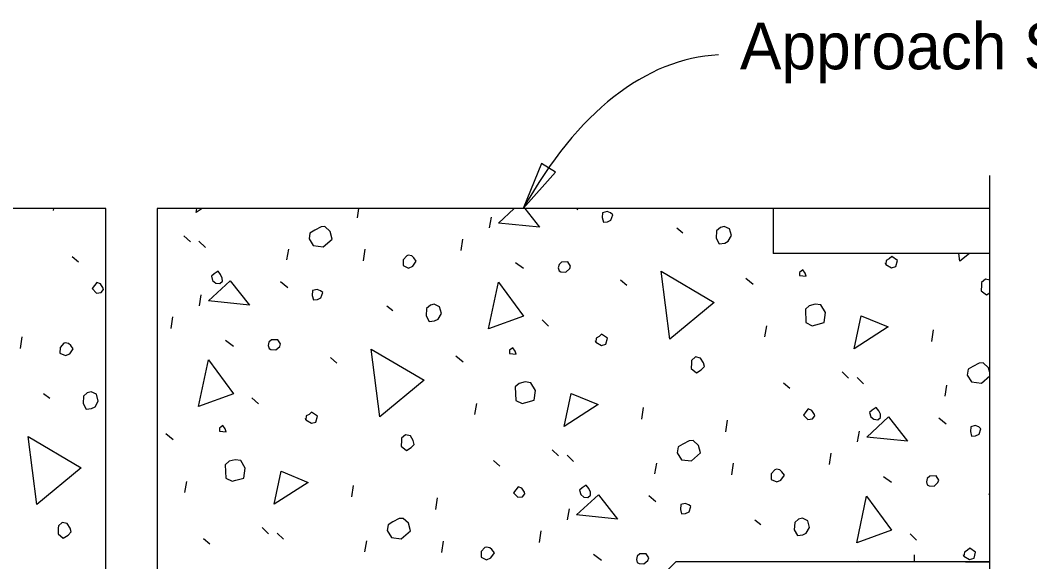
# Model space of a CAD drawing. Extents: x 112544 to 112597.1, y 111084 to 111107.1.
# Drawn here: x 112569.508 to 112572.786, y 111103.433 to 111105.19 of the extents above; entities that cross this region are included whole.
import ezdxf

# ---------------------------------------------------------------- set-up
doc = ezdxf.new("R2010")
doc.units = 0
for name, color, linetype in [('Dimension', 7, 'Continuous'), ('Miscellaneous', 7, 'Continuous'), ('SupstrConc', 7, 'Continuous'), ('TextStructures', 7, 'Continuous')]:
    doc.layers.add(name, color=color, linetype=linetype)

msp = doc.modelspace()

# ---------------------------------------------------------------- linework, layer by layer
at = {"layer": 'Dimension'}
msp.add_lwpolyline([(112571.1413, 111104.5785), (112571.2459, 111104.6974), (112571.2009, 111104.7252)], close=True, dxfattribs=at)
msp.add_lwpolyline([(112572.656, 111101.6604), (112572.656, 111101.9268), (112572.7335, 111101.9268), (112572.656, 111101.9606), (112572.5785, 111101.9943), (112572.656, 111101.9943), (112572.656, 111104.6864)], dxfattribs=at)
msp.add_ellipse((112571.8864, 111102.7097), major_axis=(0.1111, -2.3674), ratio=0.464296, start_param=3.141604, end_param=3.781059, dxfattribs=at)
at = {"layer": 'Miscellaneous'}
for p, q in [((112569.6165, 111104.5729), (112569.6175, 111104.5786)), ((112570.6036, 111104.5487), (112570.6079, 111104.5786)), ((112571.3142, 111104.5786), (112571.3188, 111104.5747)), ((112572.656, 111104.5786), (112571.9525, 111104.5786)), ((112571.0317, 111104.5159), (112571.0378, 111104.5512)), ((112571.64, 111104.5158), (112571.6596, 111104.5004)), ((112570.0394, 111104.4907), (112570.0604, 111104.4704)), ((112570.0882, 111104.4727), (112570.1092, 111104.4525)), ((112570.9402, 111104.4422), (112570.9456, 111104.4799)), ((112570.3737, 111104.412), (112570.3798, 111104.4473)), ((112570.623, 111104.409), (112570.6284, 111104.4467)), ((112569.6772, 111104.4235), (112569.6976, 111104.4056)), ((112571.1161, 111104.4039), (112571.1419, 111104.3849)), ((112570.3536, 111104.342), (112570.377, 111104.3223)), ((112571.4572, 111104.3478), (112571.4775, 111104.3299)), ((112571.8646, 111104.3534), (112571.888, 111104.3338)), ((112570.0899, 111104.2635), (112570.096, 111104.2988)), ((112570.6982, 111104.2635), (112570.7179, 111104.248)), ((112569.9984, 111104.1898), (112570.0038, 111104.2275)), ((112571.2023, 111104.2174), (112571.2233, 111104.1971)), ((112571.9261, 111104.1628), (112571.9321, 111104.1981)), ((112572.4685, 111104.1477), (112572.4739, 111104.1854)), ((112569.5088, 111104.1247), (112569.5143, 111104.1624)), ((112570.1743, 111104.1516), (112570.2001, 111104.1326)), ((112570.5154, 111104.0955), (112570.5358, 111104.0776)), ((112570.9229, 111104.1011), (112570.9462, 111104.0815)), ((112572.1766, 111104.0488), (112572.1976, 111104.0285)), ((112571.9868, 111104.0135), (112572.0071, 111103.9956)), ((112572.2254, 111104.0308), (112572.2464, 111104.0106)), ((112569.5841, 111103.9792), (112569.6037, 111103.9638)), ((112572.5109, 111103.9701), (112572.517, 111104.0054)), ((112570.2605, 111103.965), (112570.2815, 111103.9448)), ((112570.9843, 111103.9105), (112570.9904, 111103.9458)), ((112571.5267, 111103.8954), (112571.5321, 111103.9331)), ((112571.7991, 111103.8545), (112571.8045, 111103.8922)), ((112572.4908, 111103.9001), (112572.5142, 111103.8804)), ((112569.9811, 111103.8487), (112570.0045, 111103.8291)), ((112572.2271, 111103.8216), (112572.2332, 111103.8569)), ((112571.2348, 111103.7965), (112571.2558, 111103.7762)), ((112571.2837, 111103.7785), (112571.3046, 111103.7582)), ((112572.1356, 111103.7479), (112572.141, 111103.7856)), ((112571.045, 111103.7611), (112571.0653, 111103.7433)), ((112571.5691, 111103.7178), (112571.5752, 111103.7531)), ((112571.8184, 111103.7147), (112571.8238, 111103.7524)), ((112570.0425, 111103.6581), (112570.0486, 111103.6934)), ((112570.5849, 111103.643), (112570.5903, 111103.6807)), ((112572.3115, 111103.7097), (112572.3373, 111103.6907)), ((112571.5491, 111103.6477), (112571.5724, 111103.6281)), ((112572.6526, 111103.6535), (112572.656, 111103.6506)), ((112570.8573, 111103.6021), (112570.8627, 111103.6398)), ((112571.2854, 111103.5693), (112571.2914, 111103.6046)), ((112571.8936, 111103.5692), (112571.9133, 111103.5538)), ((112570.2931, 111103.5441), (112570.314, 111103.5238)), ((112570.3419, 111103.5261), (112570.3628, 111103.5059)), ((112571.1938, 111103.4956), (112571.1993, 111103.5333)), ((112572.3977, 111103.5231), (112572.4187, 111103.5028)), ((112570.1032, 111103.5088), (112570.1236, 111103.4909)), ((112570.6273, 111103.4654), (112570.6334, 111103.5007)), ((112570.8766, 111103.4624), (112570.882, 111103.5)), ((112571.3697, 111103.4573), (112571.3955, 111103.4383)), ((112572.5774, 111103.4328), (112572.656, 111103.4328))]:
    msp.add_line(p, q, dxfattribs=at)
for points in [[(112570.0788, 111104.566), (112570.0815, 111104.5786)], [(112570.0984, 111104.5786), (112570.0788, 111104.566)], [(112571.0612, 111104.5316), (112571.1118, 111104.5786)], [(112571.1462, 111104.5786), (112571.1942, 111104.518), (112571.0612, 111104.5316)], [(112571.398, 111104.5493), (112571.4019, 111104.5349), (112571.4146, 111104.5357), (112571.4261, 111104.5413), (112571.4319, 111104.5584), (112571.4251, 111104.5644), (112571.4135, 111104.569), (112571.399, 111104.5651), (112571.398, 111104.5493)], [(112570.4459, 111104.4806), (112570.4596, 111104.4584), (112570.4918, 111104.4541), (112570.5211, 111104.48), (112570.5146, 111104.5042), (112570.4974, 111104.5203), (112570.4847, 111104.5194), (112570.4642, 111104.5088), (112570.4486, 111104.4994), (112570.4459, 111104.4806)], [(112571.7693, 111104.5065), (112571.7679, 111104.4828), (112571.7779, 111104.4648), (112571.7954, 111104.4669), (112571.8069, 111104.4725), (112571.8175, 111104.4909), (112571.8116, 111104.5126), (112571.7939, 111104.5208), (112571.7818, 111104.5176), (112571.7693, 111104.5065)], [(112570.7515, 111104.4123), (112570.7512, 111104.3941), (112570.7689, 111104.3859), (112570.7827, 111104.3922), (112570.794, 111104.4082), (112570.7859, 111104.419), (112570.7792, 111104.4249), (112570.7682, 111104.4272), (112570.7634, 111104.4259), (112570.7515, 111104.4123)], [(112571.2578, 111104.3772), (112571.2639, 111104.3737), (112571.2797, 111104.3727), (112571.2923, 111104.3838), (112571.2952, 111104.3924), (112571.2865, 111104.4056), (112571.2658, 111104.4052), (112571.2575, 111104.3978), (112571.2552, 111104.3869), (112571.2578, 111104.3772)], [(112572.3187, 111104.3975), (112572.3371, 111104.3869), (112572.3516, 111104.3907), (112572.3567, 111104.4102), (112572.3377, 111104.4233), (112572.3293, 111104.4158), (112572.3203, 111104.4108), (112572.3187, 111104.3975), (112572.3174, 111104.4023)], [(112572.5593, 111104.4076), (112572.5561, 111104.4328)], [(112572.5899, 111104.4328), (112572.5593, 111104.4076)], [(112570.1328, 111104.3449), (112570.1427, 111104.3372), (112570.156, 111104.3356), (112570.1644, 111104.343), (112570.1642, 111104.3533), (112570.1586, 111104.3648), (112570.1505, 111104.3755), (112570.1373, 111104.3668), (112570.129, 111104.3594), (112570.1328, 111104.3449)], [(112571.6175, 111104.1552), (112571.5896, 111104.3755), (112571.7617, 111104.2741), (112571.6175, 111104.1552)], [(112572.0386, 111104.3612), (112572.0598, 111104.3591), (112572.0572, 111104.3688), (112572.0492, 111104.3796), (112572.0384, 111104.3715), (112572.0386, 111104.3612)], [(112569.7415, 111104.3191), (112569.7557, 111104.3047), (112569.7708, 111104.3062), (112569.7785, 111104.316), (112569.7772, 111104.3209), (112569.7685, 111104.3341), (112569.7569, 111104.3387), (112569.7492, 111104.3289), (112569.7415, 111104.3191)], [(112570.1194, 111104.2792), (112570.1899, 111104.3447), (112570.2524, 111104.2657), (112570.1194, 111104.2792)], [(112571.0287, 111104.189), (112571.0608, 111104.3399), (112571.1421, 111104.2297), (112571.0287, 111104.189)], [(112572.656, 111104.3467), (112572.6422, 111104.3495), (112572.6296, 111104.3384), (112572.6291, 111104.3305)], [(112570.4563, 111104.297), (112570.4601, 111104.2825), (112570.4729, 111104.2833), (112570.4843, 111104.289), (112570.4901, 111104.3061), (112570.4833, 111104.312), (112570.4717, 111104.3167), (112570.4572, 111104.3128), (112570.4563, 111104.297)], [(112572.6291, 111104.3305), (112572.6288, 111104.3123), (112572.6454, 111104.2987), (112572.656, 111104.305)], [(112570.8275, 111104.2541), (112570.8261, 111104.2305), (112570.8361, 111104.2124), (112570.8537, 111104.2145), (112570.8651, 111104.2202), (112570.8757, 111104.2386), (112570.8699, 111104.2603), (112570.8521, 111104.2685), (112570.8401, 111104.2653), (112570.8275, 111104.2541)], [(112572.0574, 111104.2524), (112572.0587, 111104.2087), (112572.0795, 111104.1988), (112572.0916, 111104.202), (112572.1181, 111104.2091), (112572.1224, 111104.2413), (112572.1081, 111104.266), (112572.0892, 111104.2687), (112572.0699, 111104.2635), (112572.0574, 111104.2524)], [(112572.216, 111104.1241), (112572.2391, 111104.2312), (112572.3264, 111104.195), (112572.216, 111104.1241)], [(112569.6373, 111104.1281), (112569.637, 111104.1099), (112569.6548, 111104.1017), (112569.6686, 111104.108), (112569.6799, 111104.124), (112569.6718, 111104.1347), (112569.665, 111104.1407), (112569.6541, 111104.1429), (112569.6492, 111104.1416), (112569.6373, 111104.1281)], [(112570.316, 111104.1248), (112570.3222, 111104.1213), (112570.338, 111104.1204), (112570.3505, 111104.1315), (112570.3534, 111104.14), (112570.3447, 111104.1532), (112570.3241, 111104.1529), (112570.3157, 111104.1455), (112570.3135, 111104.1345), (112570.316, 111104.1248)], [(112571.3769, 111104.1451), (112571.3953, 111104.1345), (112571.4098, 111104.1384), (112571.4149, 111104.1579), (112571.3959, 111104.1709), (112571.3876, 111104.1635), (112571.3785, 111104.1585), (112571.3769, 111104.1451), (112571.3757, 111104.1499)], [(112570.6758, 111103.9029), (112570.6478, 111104.1231), (112570.8199, 111104.0217), (112570.6758, 111103.9029)], [(112571.0968, 111104.1089), (112571.118, 111104.1068), (112571.1155, 111104.1165), (112571.1074, 111104.1272), (112571.0966, 111104.1192), (112571.0968, 111104.1089)], [(112570.087, 111103.9366), (112570.119, 111104.0876), (112570.2003, 111103.9774), (112570.087, 111103.9366)], [(112571.6874, 111104.0782), (112571.6871, 111104.06), (112571.7037, 111104.0463), (112571.7193, 111104.0557), (112571.7294, 111104.0661), (112571.7262, 111104.0782), (112571.7168, 111104.0938), (112571.7004, 111104.0972), (112571.6878, 111104.0861), (112571.6874, 111104.0782)], [(112572.656, 111104.0467), (112572.6518, 111104.0623), (112572.6346, 111104.0783), (112572.6219, 111104.0775), (112572.6014, 111104.0669), (112572.5858, 111104.0575), (112572.5831, 111104.0387)], [(112571.1156, 111104), (112571.1169, 111103.9564), (112571.1377, 111103.9464), (112571.1498, 111103.9497), (112571.1764, 111103.9568), (112571.1807, 111103.989), (112571.1663, 111104.0136), (112571.1475, 111104.0163), (112571.1281, 111104.0112), (112571.1156, 111104)], [(112572.5831, 111104.0387), (112572.5968, 111104.0165), (112572.629, 111104.0121), (112572.656, 111104.0361)], [(112569.7134, 111103.9699), (112569.712, 111103.9462), (112569.722, 111103.9282), (112569.7395, 111103.9303), (112569.7509, 111103.936), (112569.7615, 111103.9543), (112569.7557, 111103.9761), (112569.738, 111103.9842), (112569.7259, 111103.981), (112569.7134, 111103.9699)], [(112571.2742, 111103.8717), (112571.2973, 111103.9788), (112571.3846, 111103.9427), (112571.2742, 111103.8717)], [(112570.4352, 111103.8928), (112570.4535, 111103.8822), (112570.468, 111103.886), (112570.4732, 111103.9055), (112570.4541, 111103.9186), (112570.4458, 111103.9111), (112570.4368, 111103.9061), (112570.4352, 111103.8928), (112570.4339, 111103.8976)], [(112572.051, 111103.909), (112572.0652, 111103.8947), (112572.0803, 111103.8962), (112572.0881, 111103.906), (112572.0868, 111103.9108), (112572.0781, 111103.924), (112572.0665, 111103.9287), (112572.0587, 111103.9189), (112572.051, 111103.909)], [(112572.27, 111103.903), (112572.2799, 111103.8953), (112572.2932, 111103.8937), (112572.3016, 111103.9011), (112572.3014, 111103.9114), (112572.2958, 111103.9229), (112572.2877, 111103.9336), (112572.2745, 111103.9249), (112572.2662, 111103.9175), (112572.27, 111103.903)], [(112572.2566, 111103.8373), (112572.327, 111103.9028), (112572.3896, 111103.8238), (112572.2566, 111103.8373)], [(112570.155, 111103.8565), (112570.1763, 111103.8545), (112570.1737, 111103.8641), (112570.1656, 111103.8749), (112570.1548, 111103.8668), (112570.155, 111103.8565)], [(112570.7456, 111103.8258), (112570.7453, 111103.8076), (112570.7619, 111103.794), (112570.7775, 111103.8033), (112570.7876, 111103.8138), (112570.7844, 111103.8259), (112570.775, 111103.8415), (112570.7586, 111103.8448), (112570.746, 111103.8337), (112570.7456, 111103.8258)], [(112572.5935, 111103.8551), (112572.5973, 111103.8406), (112572.6101, 111103.8414), (112572.6215, 111103.8471), (112572.6273, 111103.8641), (112572.6205, 111103.8701), (112572.6089, 111103.8748), (112572.5944, 111103.8709), (112572.5935, 111103.8551)], [(112569.5616, 111103.6186), (112569.5337, 111103.8389), (112569.7058, 111103.7375), (112569.5616, 111103.6186)], [(112571.6413, 111103.7863), (112571.655, 111103.7641), (112571.6873, 111103.7598), (112571.7165, 111103.7858), (112571.7101, 111103.8099), (112571.6928, 111103.826), (112571.6801, 111103.8252), (112571.6596, 111103.8145), (112571.644, 111103.8052), (112571.6413, 111103.7863)], [(112570.1738, 111103.7477), (112570.1752, 111103.704), (112570.1959, 111103.6941), (112570.208, 111103.6973), (112570.2346, 111103.7044), (112570.2389, 111103.7366), (112570.2245, 111103.7613), (112570.2057, 111103.764), (112570.1864, 111103.7588), (112570.1738, 111103.7477)], [(112570.3324, 111103.6194), (112570.3555, 111103.7265), (112570.4428, 111103.6903), (112570.3324, 111103.6194)], [(112571.9469, 111103.7181), (112571.9466, 111103.6999), (112571.9643, 111103.6917), (112571.9782, 111103.698), (112571.9894, 111103.7139), (112571.9814, 111103.7247), (112571.9746, 111103.7307), (112571.9636, 111103.7329), (112571.9588, 111103.7316), (112571.9469, 111103.7181)], [(112571.3283, 111103.6507), (112571.3381, 111103.6429), (112571.3515, 111103.6414), (112571.3598, 111103.6488), (112571.3597, 111103.6591), (112571.354, 111103.6705), (112571.3459, 111103.6813), (112571.3327, 111103.6726), (112571.3244, 111103.6652), (112571.3283, 111103.6507)], [(112572.4532, 111103.6829), (112572.4594, 111103.6794), (112572.4752, 111103.6784), (112572.4877, 111103.6896), (112572.4906, 111103.6981), (112572.4819, 111103.7113), (112572.4613, 111103.711), (112572.4529, 111103.7035), (112572.4507, 111103.6926), (112572.4532, 111103.6829)], [(112571.1092, 111103.6567), (112571.1234, 111103.6424), (112571.1386, 111103.6438), (112571.1463, 111103.6537), (112571.145, 111103.6585), (112571.1363, 111103.6717), (112571.1247, 111103.6764), (112571.117, 111103.6665), (112571.1092, 111103.6567)], [(112571.3148, 111103.5849), (112571.3853, 111103.6504), (112571.4478, 111103.5714), (112571.3148, 111103.5849)], [(112571.6517, 111103.6027), (112571.6556, 111103.5883), (112571.6683, 111103.5891), (112571.6797, 111103.5947), (112571.6855, 111103.6118), (112571.6787, 111103.6178), (112571.6671, 111103.6224), (112571.6526, 111103.6185), (112571.6517, 111103.6027)], [(112572.2242, 111103.4947), (112572.2562, 111103.6457), (112572.3375, 111103.5354), (112572.2242, 111103.4947)], [(112569.6314, 111103.5416), (112569.6311, 111103.5234), (112569.6477, 111103.5097), (112569.6634, 111103.5191), (112569.6735, 111103.5296), (112569.6703, 111103.5416), (112569.6609, 111103.5572), (112569.6445, 111103.5606), (112569.6319, 111103.5495), (112569.6314, 111103.5416)], [(112570.6995, 111103.534), (112570.7133, 111103.5118), (112570.7455, 111103.5074), (112570.7748, 111103.5334), (112570.7683, 111103.5576), (112570.751, 111103.5736), (112570.7383, 111103.5728), (112570.7179, 111103.5622), (112570.7023, 111103.5528), (112570.6995, 111103.534)], [(112572.0229, 111103.5599), (112572.0215, 111103.5362), (112572.0315, 111103.5182), (112572.0491, 111103.5203), (112572.0605, 111103.5259), (112572.0711, 111103.5443), (112572.0653, 111103.566), (112572.0476, 111103.5742), (112572.0355, 111103.571), (112572.0229, 111103.5599)], [(112571.0051, 111103.4657), (112571.0048, 111103.4475), (112571.0225, 111103.4393), (112571.0364, 111103.4456), (112571.0476, 111103.4616), (112571.0396, 111103.4724), (112571.0328, 111103.4783), (112571.0218, 111103.4806), (112571.017, 111103.4793), (112571.0051, 111103.4657)], [(112571.5115, 111103.4306), (112571.5176, 111103.427), (112571.5334, 111103.4261), (112571.5459, 111103.4372), (112571.5488, 111103.4458), (112571.5401, 111103.459), (112571.5195, 111103.4586), (112571.5111, 111103.4512), (112571.5089, 111103.4402), (112571.5115, 111103.4306)], [(112572.4111, 111103.4549), (112572.4104, 111103.4328)], [(112572.5724, 111103.4509), (112572.5907, 111103.4402), (112572.6052, 111103.4441), (112572.6104, 111103.4636), (112572.5913, 111103.4766), (112572.583, 111103.4692), (112572.574, 111103.4642), (112572.5724, 111103.4509), (112572.5711, 111103.4557)], [(112572.2296, 111103.4328), (112572.2294, 111103.4337), (112572.2271, 111103.4328)], [(112572.303, 111103.4328), (112572.3028, 111103.433), (112572.3026, 111103.4328)]]:
    msp.add_lwpolyline(points, dxfattribs=at)
at = {"layer": 'SupstrConc'}
for p, q in [((112569.7858, 111104.5786), (112565.0089, 111104.5786)), ((112569.7858, 111102.7452), (112569.7858, 111104.5786)), ((112571.9525, 111104.5786), (112569.9525, 111104.5786)), ((112569.9525, 111104.5786), (112569.9525, 111103.2036)), ((112571.9525, 111104.5786), (112571.9525, 111104.4328)), ((112572.656, 111104.4328), (112571.9525, 111104.4328)), ((112571.4525, 111103.2481), (112571.6372, 111103.4328)), ((112572.656, 111103.4328), (112571.6372, 111103.4328))]:
    msp.add_line(p, q, dxfattribs=at)

# ---------------------------------------------------------------- texts
at = {"layer": 'TextStructures'}
msp.add_text('Approach Slab', height=0.1512, dxfattribs=at).set_placement((112571.8449, 111105.0306))

doc.saveas('drawing.dxf')
